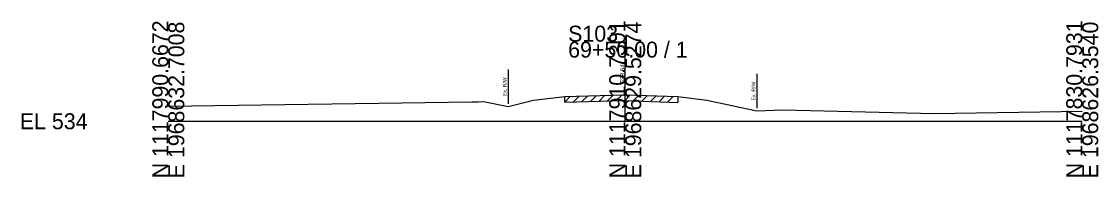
# Model space of a CAD drawing. Extents: x -26 to 163, y -10 to 24018.
# Drawn here: x -25.7 to 162.8, y 17490.3 to 17517.5 of the extents above; entities that cross this region are included whole.
import ezdxf

# ---------------------------------------------------------------- set-up
doc = ezdxf.new("R2010")
doc.units = 0
for name, color, linetype in [('RD_GPK_XS_Cell', 7, 'Continuous'), ('RD_XS_ExGround', 7, 'Continuous'), ('RD_XS_ExPaveRet', 7, 'Continuous'), ('RD_XS_ExRW', 7, 'Continuous'), ('RD_XS_TX_Elev_EX', 7, 'Continuous')]:
    doc.layers.add(name, color=color, linetype=linetype)

msp = doc.modelspace()

# ---------------------------------------------------------------- linework, layer by layer
at = {"layer": 'RD_GPK_XS_Cell'}
for p, q in [((80, 17500), (80, 17513.97)), ((0, 17500), (80, 17500)), ((80, 17500), (160, 17500))]:
    msp.add_line(p, q, dxfattribs=at)
at = {"layer": 'RD_XS_ExGround'}
msp.add_lwpolyline([(0, 17502.66), (53.11, 17503.41), (54.25, 17503.4), (55.18, 17503.44), (59.48, 17502.58), (63.96, 17503.71), (69.41, 17504.35), (75.58, 17504.54), (79.56, 17504.66), (80, 17504.64), (89.19, 17504.32), (94.28, 17503.7), (103.03, 17501.81), (104.53, 17501.88), (107.58, 17502.03), (134.07, 17501.35), (160, 17501.75)], dxfattribs=at)
at = {"layer": 'RD_XS_ExPaveRet'}
for p, q in [((69.41, 17503.35), (70.44, 17504.38)), ((69.41, 17503.35), (69.41, 17504.35)), ((69.41, 17503.35), (75.58, 17503.54)), ((70.91, 17503.4), (71.94, 17504.43)), ((72.41, 17503.44), (73.44, 17504.47)), ((73.91, 17503.49), (74.94, 17504.52)), ((75.41, 17503.53), (76.44, 17504.56)), ((75.58, 17503.54), (79.56, 17503.66)), ((76.91, 17503.58), (77.94, 17504.61)), ((78.41, 17503.62), (79.44, 17504.65)), ((79.56, 17503.66), (80, 17503.64)), ((79.91, 17503.64), (80.88, 17504.61)), ((80, 17503.64), (89.19, 17503.32)), ((81.41, 17503.59), (82.38, 17504.56)), ((82.91, 17503.54), (83.88, 17504.51)), ((84.41, 17503.49), (85.38, 17504.45)), ((85.91, 17503.43), (86.88, 17504.4)), ((87.41, 17503.38), (88.38, 17504.35)), ((89.19, 17504.32), (89.19, 17503.32))]:
    msp.add_line(p, q, dxfattribs=at)
at = {"layer": 'RD_XS_ExRW'}
for p, q in [((59.48, 17509.08), (59.48, 17503.08)), ((103.03, 17508.31), (103.03, 17502.31))]:
    msp.add_line(p, q, dxfattribs=at)

# ---------------------------------------------------------------- texts
at = {"layer": 'RD_GPK_XS_Cell'}
for s, p in [('N 1117990.6672', (0, 17490)), ('E 1968632.7008', (2.8, 17490)), ('N 1117910.7301', (80, 17490)), ('E 1968629.5274', (82.8, 17490)), ('N 1117830.7931', (160, 17490)), ('E 1968626.3540', (162.8, 17490))]:
    msp.add_text(s, height=2.8, rotation=90, dxfattribs=at).set_placement(p)
for s, p in [('S103', (70, 17513.97)), ('69+50.00 / 1', (70, 17511.17)), ('EL 534', (-26, 17498.6))]:
    msp.add_text(s, height=2.8, dxfattribs=at).set_placement(p)
at = {"layer": 'RD_XS_ExRW'}
for p in [(59.23, 17504.42), (102.78, 17503.65)]:
    msp.add_text('Ex. R/W ', height=0.65, rotation=90, dxfattribs=at).set_placement(p)
at = {"layer": 'RD_XS_TX_Elev_EX'}
msp.add_text('538.64', height=0.8, rotation=90, dxfattribs=at).set_placement((79.9, 17506.64))

doc.saveas('drawing.dxf')
